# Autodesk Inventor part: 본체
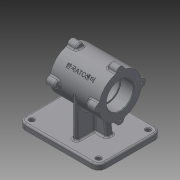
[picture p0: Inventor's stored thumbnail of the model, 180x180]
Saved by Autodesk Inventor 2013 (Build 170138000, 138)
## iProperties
Created: 2015-12
Part Number: 본체
Material: 일반
Document SubType Name: Modeling
Designer: cad8
Density: 1 g/cm^3
Author: cad8
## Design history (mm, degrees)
sketch "스케치1"
  geometry: L1 (-70, 55)-(70, 55); L2 (70, 55)-(70, -55); L3 (70, -55)-(-70, -55); L4 (-70, -55)-(-70, 55); 3 further points
  constraints: 8 end point, 2 midpoint, 2 parallel, 1 horizontal, 1 horizontal alignment, 1 perpendicular, 1 vertical alignment
  dimensions: "d0" = 140 distance of L1.start L1.end; "d2" = 110 distance of L1.end L2.end
extrude "돌출1" new body sketch "스케치1" distance "d3" = 10; taper "d4" = 0 deg
node "작업 평면1"
sketch "스케치2"
  geometry: L1 (0, 110)-(0, 0) reference; C1 r 37 at (80, 55); 1 further point
  constraints: 1 centre point, 1 horizontal alignment
  dimensions: "d6" = 74 diameter of C1; "d8" = 80 distance from line of L1 C1.centre
extrude "돌출2" join sketch "스케치2" distance "d9" = 85; taper "d10" = 0 deg
node "작업 평면2"
sketch "스케치3"
  geometry: L1 (0, 110)-(10, 110) reference; L2 (10, 110)-(10, 0) reference; L3 (10, 0)-(0, 0) reference; L4 (0, 0)-(0, 110) reference; L5 (0, 92)-(80, 92); L6 (80, 92)-(80, 18); L7 (80, 18)-(0, 18); L8 (0, 18)-(0, 92); C1 r 37 at (80, 55) reference; 1 further point
  constraints: 8 end point, 2 parallel, 2 tangent, 1 horizontal, 1 midpoint, 1 perpendicular, 1 point on line
extrude "돌출3" join sketch "스케치3" stored distance "d12" = 8; taper "d13" = 0 deg
node "작업 평면3"
hole "구멍1" diameter "d20" = 47; stored, may be unused: countersink angle "d24" = 90 deg, drill point angle "d26" = 0 deg; dims "d18" = 10, "d19" = 10, "d21" = 6, "d22" = 47, "d23" = 22, "d25" = 22
hole "구멍2" diameter "d29" = 42; stored, may be unused: countersink angle "d33" = 90 deg, drill point angle "d35" = 0 deg; dims "d27" = 10, "d28" = 10, "d30" = 6, "d31" = 47, "d32" = 22, "d34" = 41
hole "구멍3" diameter "d38" = 47; stored, may be unused: countersink angle "d42" = 90 deg, drill point angle "d44" = 0 deg; dims "d36" = 10, "d37" = 10, "d39" = 6, "d40" = 47, "d41" = 22, "d43" = 22
sketch "스케치5"
  geometry: L1 (-6, 10)-(70, 10) reference; L2 (70, 10)-(70, 0) reference; L3 (70, 0)-(-70, 0) reference; L4 (-70, 0)-(-70, 10) reference; L5 (-70, 10)-(-14, 10) reference; L6 (32.5, 43)-(-6, 43) reference; L7 (32.5, 56.5)-(32.5, 43) reference; L8 (32.5, 103.5)-(10.5, 103.5) reference; L9 (10.5, 103.5)-(10.5, 101) reference; L10 (10.5, 101)-(-30.5, 101) reference; L11 (-30.5, 101)-(-30.5, 103.5) reference; L12 (-30.5, 103.5)-(-52.5, 103.5) reference; L13 (-52.5, 43)-(-52.5, 56.5) reference; L14 (-14, 43)-(-52.5, 43) reference; L15 (-52.5, 117)-(32.5, 117) reference; L16 (32.5, 117)-(32.5, 103.5) reference; L17 (10.5, 56.5)-(32.5, 56.5) reference; L18 (10.5, 59)-(10.5, 56.5) reference; L19 (-30.5, 59)-(10.5, 59) reference; L20 (-30.5, 56.5)-(-30.5, 59) reference; L21 (-52.5, 56.5)-(-30.5, 56.5) reference; L22 (-52.5, 103.5)-(-52.5, 117) reference; L23 (-52.5, 117)-(-52.5, 124); L24 (-52.5, 124)-(-37.5, 124); L25 (-37.5, 124)-(-34.952, 117); L26 (-14, 10)-(-14, 43) reference; L27 (-6, 43)-(-6, 10) reference; 1 further point
  constraints: 6 end point, 1 collinear, 1 perpendicular, 1 point on line
  dimensions: "d45" = 110 deg angle of L15 L25; "d46" = 15 distance of L23.end L24.end; "d48" = 7 distance of L15.start L23.end
revolve "회전1" sketch "스케치5" stored, may be unused: angle "d49" = 90 deg
fillet "모깎기1" dims "d50" = 3
fillet "모깎기2" dims "d51" = 3
node "작업 평면4"
sketch "스케치6"
  geometry: A1 r 7 centre (-117, 55) between (-118.239, 61.889) and (-118.239, 48.111) reference; 2 further points
  constraints: 1 coincident
hole "구멍4" sketch "스케치6" at (-117, 55) diameter "d55" = 3.242; stored, may be unused: countersink angle "d59" = 90 deg, drill point angle "d61" = 118 deg; dims "d56" = 8, "d57" = 47, "d58" = 22, "d60" = 11
node "작업 평면5"
node "작업 평면8"
  node "작업 평면7"
sketch "스케치7"
  geometry: L1 (0, -18.921)-(0, 18.921) reference; 3 further points
  constraints: 1 horizontal alignment, 1 midpoint, 1 other
  dimensions: "d67" = 42.5 distance from line of point (42.5, 0) L1
feature "엠보싱1" sketch "스케치7" dims "d68" = 0.5, "d69" = 0
fillet "모깎기3" dims "d70" = 12
hole "구멍5" diameter "d73" = 8; stored, may be unused: countersink angle "d77" = 90 deg, drill point angle "d79" = 118 deg; dims "d71" = 10, "d72" = 10, "d74" = 8, "d75" = 47, "d76" = 22, "d78" = 11
node "작업 평면9"
fillet "모깎기8" dims "d96" = 3
fillet "모깎기9" dims "d97" = 0.3
chamfer "모따기1" distance "d98" = 1; stored, may be unused: second distance "d99" = 2, angle "d100" = 45 deg
sketch "스케치9"
  geometry: L1 (-40.526, 43)-(-41.5, 44.621) reference; L2 (-41.5, 44.621)-(-52.5, 44.621) reference; L3 (-52.5, 44.621)-(-52.5, 55.5) reference; L4 (-52.5, 55.5)-(-51.5, 56.5) reference; L5 (-51.5, 56.5)-(-30.8, 56.5) reference; L6 (-30.5, 56.8)-(-30.5, 59) reference; L7 (-30.5, 59)-(10.5, 59) reference; L8 (10.5, 59)-(10.5, 56.8) reference; L9 (10.8, 56.5)-(31.5, 56.5) reference; L10 (31.5, 56.5)-(32.5, 55.5) reference; L11 (32.5, 55.5)-(32.5, 44.621) reference; L12 (32.5, 44.621)-(21.5, 44.621) reference; L13 (21.5, 44.621)-(20.526, 43) reference; L14 (20.526, 43)-(21.5, 41.379) reference; L15 (21.5, 41.379)-(32.5, 41.379) reference; L16 (32.5, 41.379)-(32.5, 36) reference; L17 (32.5, 36)-(19.601, 36) reference; L18 (16.782, 37.974)-(15.671, 41.026) reference; L19 (12.852, 43)-(-6, 43) reference; L20 (-6, 43)-(-6, 10) reference; L21 (-6, 10)-(67, 10) reference; L22 (70, 7)-(70, 0) reference; L23 (70, 0)-(-70, 0) reference; L24 (-70, 0)-(-70, 7) reference; L25 (-67, 10)-(-14, 10) reference; L26 (-14, 10)-(-14, 43) reference; L27 (-14, 43)-(-32.852, 43) reference; L28 (-35.671, 41.026)-(-36.782, 37.974) reference; L29 (-39.601, 36)-(-52.5, 36) reference; L30 (-52.5, 36)-(-52.5, 41.379) reference; L31 (-52.5, 41.379)-(-41.5, 41.379) reference; L32 (-41.5, 41.379)-(-40.526, 43) reference; L33 (-41.5, 115.379)-(-40.526, 117) reference; L34 (-40.526, 117)-(-41.5, 118.621) reference; L35 (-41.5, 118.621)-(-52.5, 118.621) reference; L36 (-52.5, 118.621)-(-52.5, 124) reference; L37 (-52.5, 124)-(-39.601, 124) reference; L38 (-36.782, 122.026)-(-35.671, 118.974) reference; L39 (-32.852, 117)-(12.852, 117) reference; L40 (15.671, 118.974)-(16.782, 122.026) reference; L41 (19.601, 124)-(32.5, 124) reference; L42 (32.5, 124)-(32.5, 118.621) reference; L43 (32.5, 118.621)-(21.5, 118.621) reference; L44 (21.5, 118.621)-(20.526, 117) reference; L45 (20.526, 117)-(21.5, 115.379) reference; L46 (21.5, 115.379)-(32.5, 115.379) reference; L47 (32.5, 115.379)-(32.5, 104.5) reference; L48 (32.5, 104.5)-(31.5, 103.5) reference; L49 (31.5, 103.5)-(10.8, 103.5) reference; L50 (10.5, 103.2)-(10.5, 101) reference; L51 (10.5, 101)-(-30.5, 101) reference; L52 (-30.5, 101)-(-30.5, 103.2) reference; L53 (-30.8, 103.5)-(-51.5, 103.5) reference; L54 (-51.5, 103.5)-(-52.5, 104.5) reference; L55 (-52.5, 104.5)-(-52.5, 115.379) reference; L56 (-52.5, 115.379)-(-41.5, 115.379) reference; L57 (15, 10)-(10.48, 46.815); L58 (10.48, 46.815)-(-10, 46.815); L59 (-10, 46.815)-(-10, 10); L60 (-10, 10)-(15, 10); A1 r 0.3 centre (-30.8, 56.8) between (-30.8, 56.5) and (-30.5, 56.8) reference; A2 r 0.3 centre (10.8, 56.8) between (10.5, 56.8) and (10.8, 56.5) reference; A3 r 3 centre (19.601, 39) between (16.782, 37.974) and (19.601, 36) reference; A4 r 3 centre (67, 7) between (70, 7) and (67, 10) reference; A5 r 3 centre (-67, 7) between (-67, 10) and (-70, 7) reference; A6 r 3 centre (-39.601, 39) between (-39.601, 36) and (-36.782, 37.974) reference; A7 r 3 centre (-39.601, 121) between (-36.782, 122.026) and (-39.601, 124) reference; A8 r 3 centre (19.601, 121) between (19.601, 124) and (16.782, 122.026) reference; A9 r 0.3 centre (10.8, 103.2) between (10.8, 103.5) and (10.5, 103.2) reference; A10 r 0.3 centre (-30.8, 103.2) between (-30.5, 103.2) and (-30.8, 103.5) reference; 2 further points
  constraints: 8 end point, 1 collinear, 1 midpoint, 1 parallel, 1 perpendicular, 1 point on line, 1 vertical alignment, 4 other
  dimensions: "d101" = 97 deg angle of L60 L57; "d102" = 25 horizontal distance of point (-10, 117) L57.start; "d104" = 20.47966 distance of L57.end L58.end
extrude "돌출6" join sketch "스케치9" stored distance "d105" = 12; taper "d106" = 0 deg
node "작업 평면10"
fillet "모깎기10" dims "d107" = 3
fillet "모깎기11" dims "d108" = 3
fillet "모깎기12" dims "d109" = 3
fillet "모깎기13" dims "d110" = 3
fillet "모깎기14" dims "d111" = 3
fillet "모깎기15" dims "d112" = 3
chamfer "모따기2" distance "d113" = 1; stored, may be unused: second distance "d114" = 2, angle "d115" = 45 deg
node "솔리드1"
pattern_circular "원형 패턴1" dims "d53" = 360 deg
mirror "대칭2"
pattern_circular "원형 패턴2" dims angle "d63" = 360 deg
mirror "대칭3"
pattern_linear "직사각형 패턴1" dims "d82" = 86
pattern_linear "직사각형 패턴2" dims "d85" = 116
mirror "대칭5"
node "작업축1"
node "작업 평면6"
node "절단 모서리 투영1"
node "절단 모서리 투영4"
node "절단 모서리 투영6"
other parameters: "d5" = -37.5, "d66" = -45 deg
